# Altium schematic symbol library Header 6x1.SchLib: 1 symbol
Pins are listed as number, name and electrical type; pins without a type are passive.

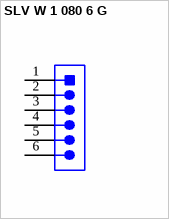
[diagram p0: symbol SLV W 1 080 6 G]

## SLV W 1 080 6 G
designator J?
Connector Header Through Hole 6 position 0.050" (1.27mm)
footprint SLV W 1 080 6 G (SULLINS)
pins: 1, 2, 3, 4, 5, 6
